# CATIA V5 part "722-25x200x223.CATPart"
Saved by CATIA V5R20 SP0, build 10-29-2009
Part number: 722-25x200x223
Definition: NONE
Nomenclature: 722-25x200x223
Source: Unknown
Description: 722-25x200x223
Bounding box of the stored display mesh (mm): x -12.5 to 12.5, y -12.5 to 12.5, z -188 to 35
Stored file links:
  C:\Users\Utente\Desktop\IO LAVORO\3D X SITO CF\X SITO\722\722-25x200x223.CATPart
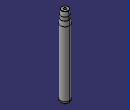
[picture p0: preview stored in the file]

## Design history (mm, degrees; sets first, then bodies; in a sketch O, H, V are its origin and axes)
Body1 "722-25x200x223" (main body)
  Solid1: solid without history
